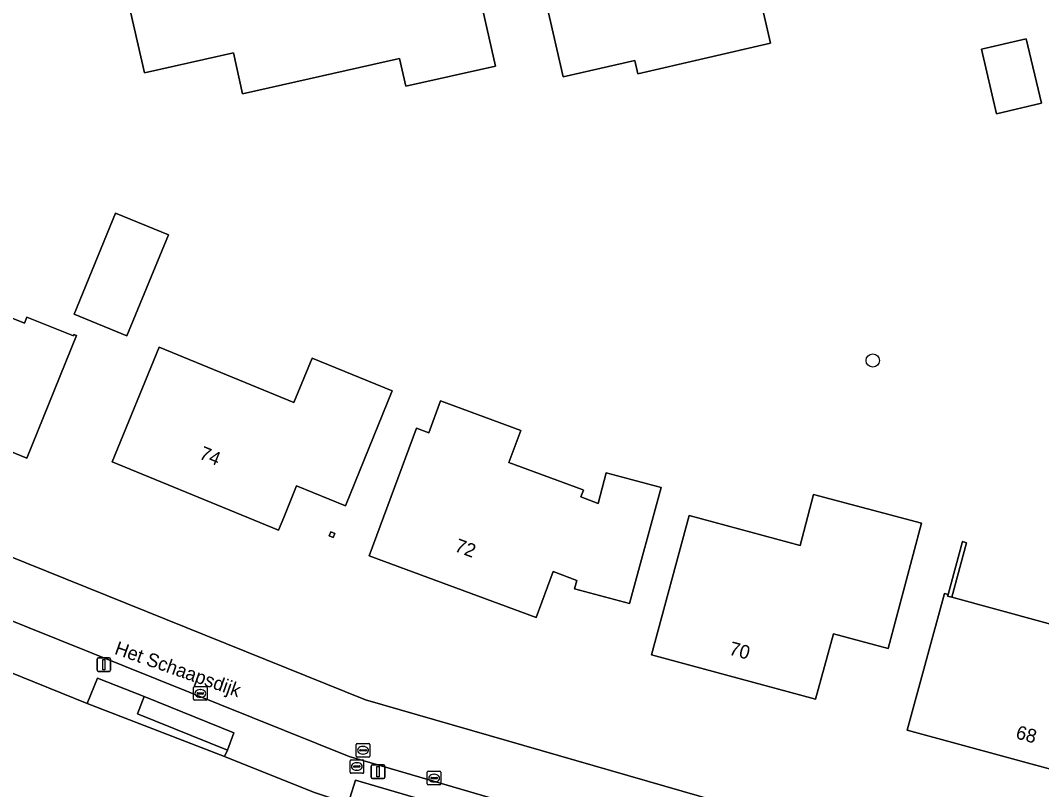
# Model space of a CAD drawing. Extents: x 156412 to 157779, y 382335 to 383768.
# Drawn here: x 156709.7 to 156784.7, y 383010.8 to 383067.3 of the extents above; entities that cross this region are included whole.
import ezdxf

# ---------------------------------------------------------------- set-up
doc = ezdxf.new("R2010")
doc.units = 0
for name, color, linetype in [('IMGEO_Boom', 7, 'Continuous'), ('IMGEO_Erf', 7, 'Continuous'), ('IMGEO_Groenvoorziening', 7, 'Continuous'), ('IMGEO_Kolk', 7, 'Continuous'), ('IMGEO_Lichtmast', 7, 'Continuous'), ('IMGEO_Muur', 7, 'Continuous'), ('IMGEO_Openbare_ruimte_label', 7, 'Continuous'), ('IMGEO_Pand', 7, 'Continuous'), ('IMGEO_Pand_nummerreeks', 7, 'Continuous'), ('IMGEO_Rijbaan_lokaal_open', 7, 'Continuous'), ('IMGEO_Rioolput', 7, 'Continuous'), ('IMGEO_Voetpad_halfverhard', 7, 'Continuous'), ('IMGEO_Voetpad_open', 7, 'Continuous')]:
    doc.layers.add(name, color=color, linetype=linetype)

msp = doc.modelspace()

# ---------------------------------------------------------------- linework, layer by layer
at = {"layer": 'IMGEO_Boom'}
msp.add_circle((156772.338, 383042.363), 0.489, dxfattribs=at)
at = {"layer": 'IMGEO_Erf'}
for points in [[(156794.644, 383096.091), (156702.248, 383074.98), (156650.985, 383063.152), (156651.041, 383062.913), (156653.965, 383050.401), (156654.02, 383050.165), (156694.029, 383033.976), (156735.088, 383017.425), (156762.167, 383009.62), (156764.546, 383008.977), (156780.193, 383004.665), (156793.034, 383001.23), (156805.108, 383066.327)], [(156707.009, 383047.318), (156706.776, 383046.422), (156710.041, 383045.098), (156710.224, 383045.549), (156713.632, 383044.174), (156713.674, 383044.276), (156713.868, 383044.198), (156710.226, 383035.19), (156705.61, 383037.069), (156705.776, 383037.52), (156699.3, 383040.169), (156702.553, 383048.126), (156703.016, 383047.936), (156703.356, 383048.791)], [(156707.889, 382982.438), (156725.856, 382986.585), (156743.843, 382990.755), (156748.534, 382991.853), (156749.422, 382994.86), (156749.313, 382994.91), (156748.992, 382994.997), (156751.561, 383004.299), (156751.637, 383004.612), (156745.29, 383006.485), (156740.437, 383007.881), (156738.669, 383008.407), (156733.812, 383009.805), (156731.259, 383010.651), (156724.744, 383013.279), (156714.643, 383017.162), (156706.878, 383020.301)]]:
    msp.add_lwpolyline(points, dxfattribs=at)
for points in [[(156749.612, 383063.194), (156748.407, 383068.438), (156747.315, 383068.189), (156744.969, 383078.475), (156746.45, 383078.817), (156746.135, 383080.187), (156749.137, 383080.885), (156749.456, 383079.491), (156754.167, 383080.57), (156755.328, 383075.542), (156757.262, 383075.986), (156757.502, 383074.931), (156762.428, 383076.064), (156764.827, 383065.658), (156755.092, 383063.414), (156754.864, 383064.404)], [(156726.064, 383061.951), (156725.384, 383064.967), (156718.852, 383063.493), (156717.573, 383069.077), (156724.107, 383070.563), (156723.422, 383073.577), (156724.483, 383073.834), (156729.415, 383074.959), (156729.699, 383073.725), (156735.591, 383075.061), (156736.438, 383071.37), (156742.658, 383072.781), (156744.642, 383063.992), (156738.053, 383062.505), (156737.591, 383064.553)], [(156780.319, 383065.218), (156783.61, 383065.986), (156784.716, 383061.251), (156781.425, 383060.482)], [(156720.609, 383051.587), (156717.566, 383044.171), (156713.691, 383045.761), (156716.735, 383053.177)], [(156731.17, 383042.54), (156737.034, 383040.128), (156733.63, 383031.688), (156730.017, 383033.147), (156729.08, 383030.828), (156728.709, 383029.91), (156716.484, 383034.92), (156719.935, 383043.34), (156729.836, 383039.283)], [(156746.489, 383037.218), (156745.621, 383034.873), (156750.995, 383032.885), (156751.098, 383032.847), (156750.911, 383032.34), (156752.162, 383031.869), (156752.769, 383034.108), (156756.796, 383033.023), (156754.484, 383024.504), (156750.444, 383025.595), (156750.611, 383026.213), (156748.866, 383026.852), (156747.615, 383023.473), (156735.361, 383028.007), (156738.831, 383037.386), (156739.732, 383037.053), (156740.599, 383039.397)], [(156778.925, 383029.06), (156779.224, 383028.979), (156778.136, 383024.976), (156788.084, 383022.272), (156789.04, 383025.79), (156788.306, 383025.989), (156791.818, 383038.648), (156799.074, 383036.63), (156797.62, 383028.763), (156797.268, 383028.838), (156793.756, 383029.832), (156791.489, 383021.485), (156792.522, 383021.204), (156789.792, 383011.155), (156774.87, 383015.211), (156777.597, 383025.245), (156777.867, 383025.171)], [(156775.916, 383030.407), (156773.471, 383021.217), (156769.447, 383022.287), (156768.141, 383017.489), (156756.083, 383020.747), (156758.847, 383030.98), (156766.997, 383028.778), (156767.991, 383032.515)], [(156732.538, 383029.773), (156732.827, 383029.659), (156732.71, 383029.365), (156732.423, 383029.48)]]:
    msp.add_lwpolyline(points, close=True, dxfattribs=at)
at = {"layer": 'IMGEO_Groenvoorziening'}
for points in [[(156715.395, 383019.036), (156714.643, 383017.162), (156724.744, 383013.279), (156724.941, 383013.742), (156718.351, 383016.41), (156718.83, 383017.694)], [(156739.2, 383010.121), (156734.35, 383011.541), (156733.94, 383010.218), (156738.792, 383008.803)]]:
    msp.add_lwpolyline(points, close=True, dxfattribs=at)
at = {"layer": 'IMGEO_Kolk'}
for p, q in [((156722.455, 383017.482), (156722.455, 383018.334)), ((156722.53, 383018.408), (156723.382, 383018.408)), ((156722.714, 383017.902), (156722.714, 383017.914)), ((156723.152, 383017.865), (156722.754, 383017.865)), ((156722.757, 383017.951), (156723.155, 383017.951)), ((156722.943, 383018.188), (156722.968, 383018.188)), ((156723.198, 383017.914), (156723.198, 383017.902)), ((156723.456, 383018.334), (156723.456, 383017.482)), ((156723.382, 383017.408), (156722.53, 383017.408)), ((156722.966, 383017.628), (156722.941, 383017.628)), ((156739.626, 383011.263), (156739.626, 383012.115)), ((156739.701, 383012.189), (156740.553, 383012.189)), ((156740.114, 383011.969), (156740.139, 383011.969)), ((156740.627, 383012.115), (156740.627, 383011.263)), ((156740.553, 383011.189), (156739.701, 383011.189)), ((156739.885, 383011.683), (156739.885, 383011.695)), ((156740.323, 383011.646), (156739.925, 383011.646)), ((156739.928, 383011.732), (156740.326, 383011.732)), ((156740.137, 383011.409), (156740.112, 383011.409)), ((156740.369, 383011.695), (156740.369, 383011.683))]:
    msp.add_line(p, q, dxfattribs=at)
for points in [[(156722.455, 383017.482), (156722.455, 383018.334)], [(156722.53, 383018.408), (156723.382, 383018.408)], [(156723.456, 383018.334), (156723.456, 383017.482)], [(156723.382, 383017.408), (156722.53, 383017.408)], [(156739.626, 383011.263), (156739.626, 383012.115)], [(156739.701, 383012.189), (156740.553, 383012.189)], [(156740.627, 383012.115), (156740.627, 383011.263)], [(156740.553, 383011.189), (156739.701, 383011.189)]]:
    msp.add_lwpolyline(points, dxfattribs=at)
for centre, radius, start, end in [((156722.532, 383018.332), 0.0765, 91.55205, 178.44795), ((156722.532, 383018.332), 0.0765, 91.55205, 178.44795), ((156722.754, 383017.911), 0.0403, 85.87752, 175.75265), ((156722.751, 383017.901), 0.0366, 178.93798, 274.71019), ((156723.155, 383017.908), 0.043, 264.86636, 352.45326), ((156723.159, 383017.913), 0.0386, 1.73085, 96.63898), ((156723.38, 383018.332), 0.0765, 1.55205, 88.44795), ((156723.38, 383018.332), 0.0765, 1.55205, 88.44795), ((156722.532, 383017.484), 0.0765, 181.55205, 268.44795), ((156722.532, 383017.484), 0.0765, 181.55205, 268.44795), ((156723.38, 383017.484), 0.0765, 271.55205, 358.44795), ((156723.38, 383017.484), 0.0765, 271.55205, 358.44795), ((156739.703, 383012.113), 0.0765, 91.55205, 178.44795), ((156739.703, 383012.113), 0.0765, 91.55205, 178.44795), ((156740.551, 383012.113), 0.0765, 1.55205, 88.44795), ((156740.551, 383012.113), 0.0765, 1.55205, 88.44795), ((156739.703, 383011.265), 0.0765, 181.55205, 268.44795), ((156739.703, 383011.265), 0.0765, 181.55205, 268.44795), ((156739.925, 383011.692), 0.0403, 85.87752, 175.75265), ((156739.922, 383011.682), 0.0366, 178.93798, 274.71019), ((156740.326, 383011.689), 0.043, 264.86636, 352.45326), ((156740.33, 383011.694), 0.0386, 1.73085, 96.63898), ((156740.551, 383011.265), 0.0765, 271.55205, 358.44795), ((156740.551, 383011.265), 0.0765, 271.55205, 358.44795)]:
    msp.add_arc(centre, radius, start, end, dxfattribs=at)
for centre, major_axis, ratio, start_param, end_param in [((156722.942, 383017.908), (-0.387, 0.002), 0.722429, 4.712389, 7.853982), ((156722.967, 383017.908), (-0.39, 0.002), 0.717154, 1.570796, 4.712389), ((156740.113, 383011.689), (-0.387, 0.002), 0.722429, 4.712389, 7.853982), ((156740.138, 383011.689), (-0.39, 0.002), 0.717154, 1.570796, 4.712389)]:
    msp.add_ellipse(centre, major_axis=major_axis, ratio=ratio, start_param=start_param, end_param=end_param, dxfattribs=at)
at = {"layer": 'IMGEO_Lichtmast'}
for p, q in [((156715.377, 383019.626), (156715.377, 383020.426)), ((156715.377, 383020.426), (156715.377, 383019.626)), ((156715.477, 383020.526), (156716.267, 383020.526)), ((156716.267, 383020.526), (156715.477, 383020.526)), ((156716.367, 383020.426), (156716.367, 383019.626)), ((156716.367, 383019.626), (156716.367, 383020.426)), ((156716.267, 383019.526), (156715.477, 383019.526)), ((156715.477, 383019.526), (156716.267, 383019.526)), ((156735.61, 383012.663), (156736.4, 383012.663)), ((156736.4, 383012.663), (156735.61, 383012.663)), ((156735.51, 383011.763), (156735.51, 383012.563)), ((156735.51, 383012.563), (156735.51, 383011.763)), ((156736.5, 383012.563), (156736.5, 383011.763)), ((156736.5, 383011.763), (156736.5, 383012.563)), ((156736.4, 383011.663), (156735.61, 383011.663)), ((156735.61, 383011.663), (156736.4, 383011.663))]:
    msp.add_line(p, q, dxfattribs=at)
for points in [[(156715.797, 383020.401), (156715.947, 383020.401), (156715.947, 383019.651), (156715.797, 383019.651), (156715.797, 383020.401)], [(156735.93, 383012.538), (156736.08, 383012.538), (156736.08, 383011.788), (156735.93, 383011.788), (156735.93, 383012.538)]]:
    msp.add_lwpolyline(points, dxfattribs=at)
for centre, start, end in [((156715.477, 383020.426), 90, 180), ((156715.477, 383020.426), 90, 180), ((156716.267, 383020.426), 0, 90), ((156716.267, 383020.426), 360, 90), ((156715.477, 383019.626), 180, 270), ((156715.477, 383019.626), 180, 270), ((156716.267, 383019.626), 270, 0), ((156716.267, 383019.626), 270, 0), ((156735.61, 383012.563), 90, 180), ((156735.61, 383012.563), 90, 180), ((156736.4, 383012.563), 0, 90), ((156736.4, 383012.563), 360, 90), ((156735.61, 383011.763), 180, 270), ((156735.61, 383011.763), 180, 270), ((156736.4, 383011.763), 270, 0), ((156736.4, 383011.763), 270, 0)]:
    msp.add_arc(centre, 0.1, start, end, dxfattribs=at)
at = {"layer": 'IMGEO_Muur'}
for points in [[(156732.423, 383029.48), (156732.538, 383029.773), (156732.827, 383029.659)], [(156732.827, 383029.659), (156732.71, 383029.365), (156732.423, 383029.48)]]:
    msp.add_lwpolyline(points, dxfattribs=at)
msp.add_lwpolyline([(156778.925, 383029.06), (156777.867, 383025.171), (156777.836, 383025.058), (156778.136, 383024.976), (156779.224, 383028.979)], close=True, dxfattribs=at)
at = {"layer": 'IMGEO_Pand'}
for points in [[(156749.612, 383063.194), (156754.864, 383064.404), (156755.092, 383063.414), (156764.827, 383065.658), (156762.428, 383076.064), (156757.502, 383074.931), (156757.262, 383075.986), (156755.328, 383075.542), (156754.167, 383080.57), (156749.456, 383079.491), (156749.137, 383080.885), (156746.135, 383080.187), (156746.45, 383078.817), (156744.969, 383078.475), (156747.315, 383068.189), (156748.407, 383068.438)], [(156729.699, 383073.725), (156729.415, 383074.959), (156724.483, 383073.834), (156723.422, 383073.577), (156724.107, 383070.563), (156717.573, 383069.077), (156718.852, 383063.493), (156725.384, 383064.967), (156726.064, 383061.951), (156737.591, 383064.553), (156738.053, 383062.505), (156744.642, 383063.992), (156742.658, 383072.781), (156736.438, 383071.37), (156735.591, 383075.061)], [(156780.319, 383065.218), (156781.425, 383060.482), (156784.716, 383061.251), (156783.61, 383065.986)], [(156717.566, 383044.171), (156720.609, 383051.587), (156716.735, 383053.177), (156713.691, 383045.761)], [(156729.08, 383030.828), (156730.017, 383033.147), (156733.63, 383031.688), (156737.034, 383040.128), (156731.17, 383042.54), (156729.836, 383039.283), (156719.935, 383043.34), (156716.484, 383034.92), (156728.709, 383029.91)], [(156750.995, 383032.885), (156745.621, 383034.873), (156746.489, 383037.218), (156740.599, 383039.397), (156739.732, 383037.053), (156738.831, 383037.386), (156735.361, 383028.007), (156747.615, 383023.473), (156748.866, 383026.852), (156750.611, 383026.213), (156750.444, 383025.595), (156754.484, 383024.504), (156756.796, 383033.023), (156752.769, 383034.108), (156752.162, 383031.869), (156750.911, 383032.34), (156751.098, 383032.847)], [(156792.522, 383021.204), (156791.489, 383021.485), (156793.756, 383029.832), (156797.268, 383028.838), (156797.62, 383028.763), (156799.074, 383036.63), (156791.818, 383038.648), (156788.306, 383025.989), (156789.04, 383025.79), (156788.084, 383022.272), (156778.136, 383024.976), (156777.836, 383025.058), (156777.867, 383025.171), (156777.597, 383025.245), (156774.87, 383015.211), (156789.792, 383011.155)], [(156775.916, 383030.407), (156767.991, 383032.515), (156766.997, 383028.778), (156758.847, 383030.98), (156756.083, 383020.747), (156768.141, 383017.489), (156769.447, 383022.287), (156773.471, 383021.217)], [(156732.538, 383029.773), (156732.423, 383029.48), (156732.71, 383029.365), (156732.827, 383029.659)]]:
    msp.add_lwpolyline(points, close=True, dxfattribs=at)
msp.add_lwpolyline([(156703.356, 383048.791), (156703.016, 383047.936), (156702.553, 383048.126), (156699.3, 383040.169), (156705.776, 383037.52), (156705.61, 383037.069), (156710.226, 383035.19), (156713.868, 383044.198), (156713.674, 383044.276), (156713.632, 383044.174), (156710.224, 383045.549), (156710.041, 383045.098), (156706.776, 383046.422), (156707.009, 383047.318)], dxfattribs=at)
at = {"layer": 'IMGEO_Rijbaan_lokaal_open'}
msp.add_lwpolyline([(156807.482, 382997.049), (156801.112, 382998.951), (156797.441, 383000), (156796.468, 383000.278), (156794.66, 383000.795), (156793.034, 383001.23), (156780.193, 383004.665), (156764.546, 383008.977), (156762.167, 383009.62), (156735.088, 383017.425), (156694.029, 383033.976), (156654.02, 383050.165), (156648.989, 383052.201), (156649.969, 383047.802), (156650.109, 383047.168), (156689.001, 383031.323), (156733.896, 383013.266), (156757.494, 383006.379)], dxfattribs=at)
at = {"layer": 'IMGEO_Rioolput'}
for p, q in [((156734.406, 383013.305), (156734.406, 383014.157)), ((156734.481, 383014.231), (156735.333, 383014.231)), ((156735.407, 383014.157), (156735.407, 383013.305)), ((156734.665, 383013.725), (156734.665, 383013.737)), ((156735.103, 383013.688), (156734.705, 383013.688)), ((156734.708, 383013.774), (156735.106, 383013.774)), ((156734.917, 383013.451), (156734.892, 383013.451)), ((156734.894, 383014.011), (156734.919, 383014.011)), ((156735.149, 383013.737), (156735.149, 383013.725)), ((156733.951, 383012.113), (156733.951, 383012.965)), ((156734.026, 383013.039), (156734.878, 383013.039)), ((156734.439, 383012.819), (156734.464, 383012.819)), ((156735.333, 383013.231), (156734.481, 383013.231)), ((156734.952, 383012.965), (156734.952, 383012.113)), ((156734.878, 383012.039), (156734.026, 383012.039)), ((156734.21, 383012.533), (156734.21, 383012.545)), ((156734.648, 383012.496), (156734.25, 383012.496)), ((156734.253, 383012.582), (156734.651, 383012.582)), ((156734.462, 383012.259), (156734.437, 383012.259)), ((156734.694, 383012.545), (156734.694, 383012.533))]:
    msp.add_line(p, q, dxfattribs=at)
for points in [[(156734.406, 383013.305), (156734.406, 383014.157)], [(156734.481, 383014.231), (156735.333, 383014.231)], [(156735.407, 383014.157), (156735.407, 383013.305)], [(156733.951, 383012.113), (156733.951, 383012.965)], [(156734.026, 383013.039), (156734.878, 383013.039)], [(156735.333, 383013.231), (156734.481, 383013.231)], [(156734.952, 383012.965), (156734.952, 383012.113)], [(156734.878, 383012.039), (156734.026, 383012.039)]]:
    msp.add_lwpolyline(points, dxfattribs=at)
for centre, radius, start, end in [((156734.483, 383014.155), 0.0765, 91.55205, 178.44795), ((156734.483, 383014.155), 0.0765, 91.55205, 178.44795), ((156735.331, 383014.155), 0.0765, 1.55205, 88.44795), ((156735.331, 383014.155), 0.0765, 1.55205, 88.44795), ((156734.705, 383013.734), 0.0403, 85.87752, 175.75265), ((156734.702, 383013.724), 0.0366, 178.93798, 274.71019), ((156735.106, 383013.731), 0.043, 264.86636, 352.45326), ((156735.11, 383013.736), 0.0386, 1.73085, 96.63898), ((156734.028, 383012.963), 0.0765, 91.55205, 178.44795), ((156734.028, 383012.963), 0.0765, 91.55205, 178.44795), ((156734.483, 383013.307), 0.0765, 181.55205, 268.44795), ((156734.483, 383013.307), 0.0765, 181.55205, 268.44795), ((156734.876, 383012.963), 0.0765, 1.55205, 88.44795), ((156734.876, 383012.963), 0.0765, 1.55205, 88.44795), ((156735.331, 383013.307), 0.0765, 271.55205, 358.44795), ((156735.331, 383013.307), 0.0765, 271.55205, 358.44795), ((156734.028, 383012.115), 0.0765, 181.55205, 268.44795), ((156734.028, 383012.115), 0.0765, 181.55205, 268.44795), ((156734.25, 383012.542), 0.0403, 85.87752, 175.75265), ((156734.247, 383012.532), 0.0366, 178.93798, 274.71019), ((156734.651, 383012.539), 0.043, 264.86636, 352.45326), ((156734.655, 383012.544), 0.0386, 1.73085, 96.63898), ((156734.876, 383012.115), 0.0765, 271.55205, 358.44795), ((156734.876, 383012.115), 0.0765, 271.55205, 358.44795)]:
    msp.add_arc(centre, radius, start, end, dxfattribs=at)
for centre, major_axis, ratio, start_param, end_param in [((156734.893, 383013.731), (-0.387, 0.002), 0.722429, 4.712389, 7.853982), ((156734.918, 383013.731), (-0.39, 0.002), 0.717154, 1.570796, 4.712389), ((156734.438, 383012.539), (-0.387, 0.002), 0.722429, 4.712389, 7.853982), ((156734.463, 383012.539), (-0.39, 0.002), 0.717154, 1.570796, 4.712389)]:
    msp.add_ellipse(centre, major_axis=major_axis, ratio=ratio, start_param=start_param, end_param=end_param, dxfattribs=at)
at = {"layer": 'IMGEO_Voetpad_halfverhard'}
msp.add_lwpolyline([(156718.83, 383017.694), (156718.351, 383016.41), (156724.941, 383013.742), (156725.422, 383015.014)], close=True, dxfattribs=at)
at = {"layer": 'IMGEO_Voetpad_open'}
for points in [[(156733.896, 383013.266), (156689.001, 383031.323), (156650.109, 383047.168)], [(156706.878, 383020.301), (156714.643, 383017.162), (156715.395, 383019.036), (156718.83, 383017.694), (156725.422, 383015.014), (156724.941, 383013.742), (156724.744, 383013.279), (156731.259, 383010.651), (156733.812, 383009.805), (156733.94, 383010.218), (156734.35, 383011.541), (156739.2, 383010.121), (156738.792, 383008.803), (156738.669, 383008.407), (156740.437, 383007.881), (156740.514, 383008.303), (156740.922, 383009.613), (156745.771, 383008.187), (156745.425, 383006.928), (156745.29, 383006.485), (156751.637, 383004.612), (156752.14, 383006.32), (156756.674, 383005.046), (156757.474, 383004.813)], [(156757.494, 383006.379), (156733.896, 383013.266)]]:
    msp.add_lwpolyline(points, dxfattribs=at)

# ---------------------------------------------------------------- texts
at = {"layer": 'IMGEO_Openbare_ruimte_label'}
msp.add_text('Het Schaapsdijk', height=1, rotation=340.60447, dxfattribs=at).set_placement((156716.592, 383020.826))
at = {"layer": 'IMGEO_Pand_nummerreeks'}
for s, rotation, p in [('74', 337.70415, (156722.806, 383035.177)), ('72', 339.50409, (156741.559, 383028.375)), ('70', 344.87964, (156761.723, 383020.777)), ('68', 344.7937, (156782.775, 383014.617))]:
    msp.add_text(s, height=1, rotation=rotation, dxfattribs=at).set_placement(p)

doc.saveas('drawing.dxf')
